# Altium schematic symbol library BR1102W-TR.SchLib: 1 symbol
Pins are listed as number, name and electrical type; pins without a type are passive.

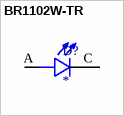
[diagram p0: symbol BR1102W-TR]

## BR1102W-TR
designator D?
LED Uni-Color Red 660nm 2-Pin SMD T/R; MP: BR1102W-TR
footprint LED_BR1102W-TR
pins: A, C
